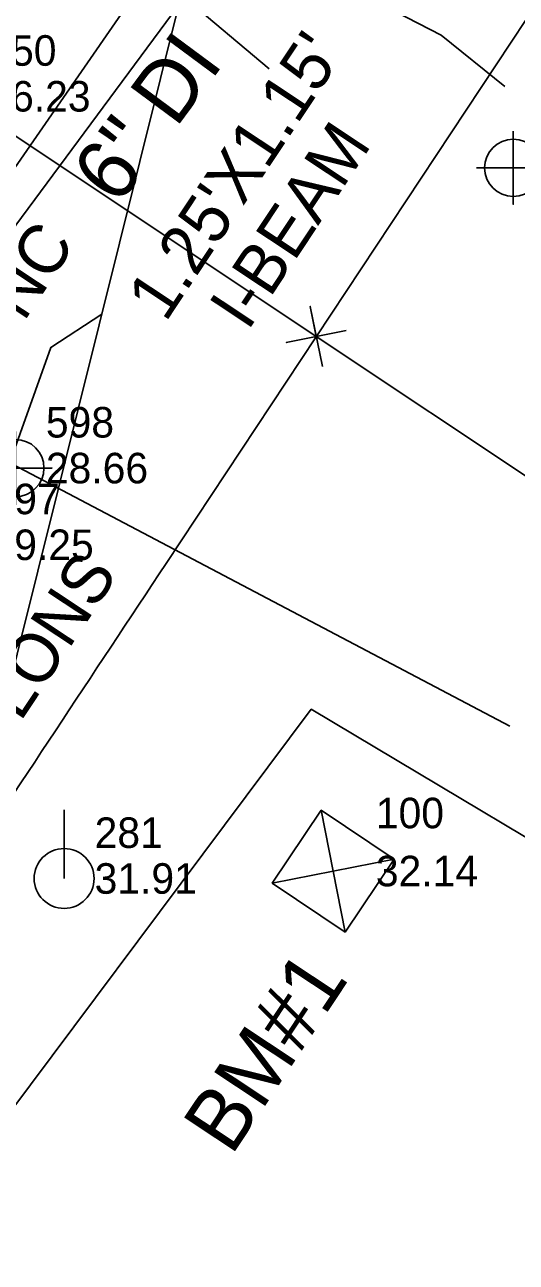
# Model space of a CAD drawing. Extents: x 2603627 to 2605187, y 896619 to 899063.
# Drawn here: x 2604567.5 to 2604607.7, y 898066.2 to 898167.5 of the extents above; entities that cross this region are included whole.
import ezdxf

# ---------------------------------------------------------------- set-up
doc = ezdxf.new("R2010")
doc.units = 0
for name, color, linetype in [('CTL Bench Mark CELL', 7, 'Continuous'), ('CTL Bench Mark Cogo Elevation', 7, 'Continuous'), ('CTL Bench Mark Cogo Number', 7, 'Continuous'), ('CTL Bench Mark Text', 7, 'Continuous'), ('Default Symbol CELL', 7, 'Continuous'), ('Exist DTM Drainline Cogo Elevation', 7, 'Continuous'), ('Exist DTM Drainline Cogo Number', 7, 'Continuous'), ('Exist DTM Drainline Cogo Point CELL', 7, 'Continuous'), ('Exist Horizontal Baseline Alignment', 7, 'Continuous'), ('Exist Hydro Stream or Body of Water', 7, 'Continuous'), ('Exist Other Culture Located Object Text', 7, 'Continuous'), ('Exist Property Corner CELL', 7, 'Continuous'), ('Exist Property Line', 7, 'Continuous'), ('Exist Property Tie Line', 7, 'Continuous'), ('Exist Property Tie Line Leader', 7, 'Continuous'), ('Exist Right of Way Line', 7, 'Continuous'), ('Exist Structure Major Bridge Seam Cogo Elevation', 7, 'Continuous'), ('Exist Structure Major Bridge Seam Cogo Number', 7, 'Continuous'), ('Exist Structure Major Bridge Topo Leader', 7, 'Continuous'), ('Exist Structure Major Bridge Topo Text', 7, 'Continuous'), ('Exist Structure Major Bridge WW Text', 7, 'Continuous'), ('Exist Utilities Power Pole CELL', 7, 'Continuous'), ('Exist Utilities Power Pole Cogo Elevation', 7, 'Continuous'), ('Exist Utilities Power Pole Cogo Number', 7, 'Continuous'), ('Exist Utilities Water UG Line SUE LOS C', 7, 'Continuous'), ('Exist Utilities Water UG Line SUE LOS C Text', 7, 'Continuous'), ('Exist Vegetation Woods Line', 7, 'Continuous')]:
    doc.layers.add(name, color=color, linetype=linetype)

# ---------------------------------------------------------------- blocks, each defined once
blk = doc.blocks.new('CTL BENCH MARK')
at = {"layer": 'CTL Bench Mark CELL'}
blk.add_line((0, 0), (0, 0), dxfattribs=at)
blk.add_lwpolyline([(-0.072, 0.07175), (0.07175, 0.07175), (0.07175, -0.072), (-0.072, -0.072)], close=True, dxfattribs=at)
for points in [[(0.07175, 0.07175), (-0.072, -0.072), (-0.000125, -0.000125), (0.07175, -0.072), (-0.072, 0.07175)], [(-0.000125, -0.000125), (0.07175, 0.07175), (-0.072, 0.07175), (-0.000125, -0.000125)], [(-0.000125, -0.000125), (-0.072, -0.072), (0.07175, -0.072), (-0.000125, -0.000125)]]:
    blk.add_lwpolyline(points, dxfattribs=at)
blk = doc.blocks.new('DEFAULT SYMBOL')
at = {"layer": 'Default Symbol CELL'}
blk.add_lwpolyline([(0, 0.06), (0, -0.06), (0, 0), (0.06, 0), (-0.06, 0)], dxfattribs=at)
blk.add_circle((0, 0), 0.0469, dxfattribs=at)
blk = doc.blocks.new('EXIST DTM DRAINLINE COGO POINT')
at = {"layer": 'Exist DTM Drainline Cogo Point CELL'}
blk.add_lwpolyline([(0, 0.06), (0, -0.06), (0, 0), (0.06, 0), (-0.06, 0)], dxfattribs=at)
blk.add_circle((0, 0), 0.0469, dxfattribs=at)

msp = doc.modelspace()

# ---------------------------------------------------------------- linework, layer by layer
at = {"layer": 'Exist Horizontal Baseline Alignment'}
msp.add_line((2604544.96, 898124.44), (2604793.6, 898483.9), dxfattribs=at)
at = {"layer": 'Exist Hydro Stream or Body of Water'}
for points in [[(2604579.03, 898178.3), (2604601.56, 898166.67)], [(2604601.56, 898166.67), (2604606.78, 898162.46)], [(2604566.47, 898131.55), (2604607.18, 898110.11)]]:
    msp.add_lwpolyline(points, dxfattribs=at)
at = {"layer": 'Exist Property Corner CELL'}
msp.add_line((2604591.34, 898142.01), (2604591.34, 898142.01), dxfattribs=at)
msp.add_lwpolyline([(2604591.84, 898139.56), (2604590.85, 898144.46), (2604591.34, 898142.01), (2604588.89, 898141.51), (2604593.79, 898142.5)], dxfattribs=at)
at = {"layer": 'Exist Property Line'}
msp.add_line((2604591.34, 898142.01), (2604711.48, 898061.89), dxfattribs=at)
at = {"layer": 'Exist Property Tie Line'}
for p, q in [((2604598.89, 898244.52), (2604562.45, 898098.35)), ((2604549.45, 898169.94), (2604591.34, 898142.01))]:
    msp.add_line(p, q, dxfattribs=at)
at = {"layer": 'Exist Property Tie Line Leader'}
msp.add_lwpolyline([(2604573.79, 898143.82), (2604569.62, 898141.11), (2604502.96, 897954.22), (2604488.28, 897929.59)], dxfattribs=at)
at = {"layer": 'Exist Right of Way Line'}
msp.add_line((2604579.05, 898123.42), (2604689.46, 898290.33), dxfattribs=at)
msp.add_arc((2574512.68, 918013.51), 36050, 326.409433, 326.513795, dxfattribs=at)
at = {"layer": 'Exist Structure Major Bridge Topo Leader'}
msp.add_line((2604575.03, 898174.4), (2604587.48, 898163.92), dxfattribs=at)
at = {"layer": 'Exist Utilities Power Pole CELL'}
for q in [(2604570.7, 898103.26), (2604570.7, 898097.63)]:
    msp.add_line((2604570.7, 898097.63), q, dxfattribs=at)
msp.add_circle((2604570.7, 898097.63), 2.45, dxfattribs=at)
at = {"layer": 'Exist Utilities Water UG Line SUE LOS C'}
msp.add_line((2604550.55, 898129.28), (2604590.41, 898183.07), dxfattribs=at)
at = {"layer": 'Exist Vegetation Woods Line'}
msp.add_lwpolyline([(2604559.06, 898068.86), (2604590.93, 898111.48), (2604620.63, 898093.76)], dxfattribs=at)

# ---------------------------------------------------------------- block references
at = {"layer": 'CTL Bench Mark CELL', "xscale": 50.000000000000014, "yscale": 50.00000000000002, "rotation": 56.07464692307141}
msp.add_blockref('CTL BENCH MARK', (2604592.72, 898098.24), dxfattribs=at)
at = {"layer": 'Default Symbol CELL', "xscale": 50, "yscale": 50}
msp.add_blockref('DEFAULT SYMBOL', (2604607.47, 898155.81), dxfattribs=at)
at = {"layer": 'Exist DTM Drainline Cogo Point CELL', "xscale": 50, "yscale": 50}
msp.add_blockref('EXIST DTM DRAINLINE COGO POINT', (2604566.71, 898131.23), dxfattribs=at)

# ---------------------------------------------------------------- texts
at = {"layer": 'CTL Bench Mark Cogo Elevation'}
msp.add_text('32.14', height=2.5, dxfattribs=at).set_placement((2604596.22, 898096.99))
at = {"layer": 'CTL Bench Mark Cogo Number'}
msp.add_text('100', height=2.5, dxfattribs=at).set_placement((2604596.22, 898101.74))
at = {"layer": 'CTL Bench Mark Text'}
msp.add_text('BM#1', height=5, rotation=56.4094, dxfattribs=at).set_placement((2604584.39, 898074.84))
at = {"layer": 'Exist DTM Drainline Cogo Elevation'}
for s, p in [('28.66', (2604569.21, 898129.98)), ('29.25', (2604564.76, 898123.7))]:
    msp.add_text(s, height=2.5, dxfattribs=at).set_placement(p)
at = {"layer": 'Exist DTM Drainline Cogo Number'}
for s, p in [('598', (2604569.21, 898133.73)), ('597', (2604564.76, 898127.45))]:
    msp.add_text(s, height=2.5, dxfattribs=at).set_placement(p)
at = {"layer": 'Exist Other Culture Located Object Text'}
msp.add_text('WD PYLONS', height=4, rotation=56.4785, dxfattribs=at).set_placement((2604557.44, 898095.77))
at = {"layer": 'Exist Structure Major Bridge Seam Cogo Elevation'}
msp.add_text('36.23', height=2.5, dxfattribs=at).set_placement((2604564.5, 898160.42))
at = {"layer": 'Exist Structure Major Bridge Seam Cogo Number'}
msp.add_text('750', height=2.5, dxfattribs=at).set_placement((2604564.5, 898164.17))
at = {"layer": 'Exist Structure Major Bridge Topo Text'}
for s, p in [("1.25'X1.15'", (2604579, 898143.09)), ('I-BEAM', (2604585.73, 898142.37))]:
    msp.add_text(s, height=4, rotation=56.4094, dxfattribs=at).set_placement(p)
at = {"layer": 'Exist Structure Major Bridge WW Text'}
msp.add_text('CONC', height=4, rotation=56.4785, dxfattribs=at).set_placement((2604562.97, 898136.45))
at = {"layer": 'Exist Utilities Power Pole Cogo Elevation'}
msp.add_text('31.91', height=2.5, dxfattribs=at).set_placement((2604573.2, 898096.38))
at = {"layer": 'Exist Utilities Power Pole Cogo Number'}
msp.add_text('281', height=2.5, dxfattribs=at).set_placement((2604573.2, 898100.13))
at = {"layer": 'Exist Utilities Water UG Line SUE LOS C Text'}
msp.add_text('6" DI', height=5, rotation=53.4619, dxfattribs=at).set_placement((2604575.11, 898152.61))

doc.saveas('drawing.dxf')
